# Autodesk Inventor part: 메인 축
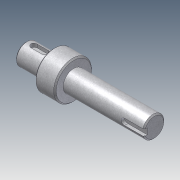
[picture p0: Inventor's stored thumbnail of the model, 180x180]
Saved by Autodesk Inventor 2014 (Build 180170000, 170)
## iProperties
Company: 한국ATC센터
Created: 2014-10
Part Number: 메인 축
Document SubType Name: Modeling
Designer: KYOUNG IL JANG
Density: 1 g/cm^3
Mass: 29.2926 g
Surface Area: 74.3518 cm^2
Volume: 29.2926 cm^3
Material: 일반
Appearance: 금속-강(스테인리스, 브러시됨)
Author: KYOUNG IL JANG
Revision Number: 1
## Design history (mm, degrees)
sketch "스케치1"
  geometry: L1 (10.497, -57.5)-(112.497, -57.5); L2 (10.497, -66)-(32.497, -66); L3 (32.497, -72.5)-(46.5, -72.5); L4 (46.5, -66)-(112.497, -66); L5 (112.497, -66)-(112.497, -57.5); L6 (10.497, -66)-(10.497, -57.5); L7 (46.5, -69.749)-(46.5, -45.251) reference; L8 (46.5, -72.5)-(46.5, -66); L9 (32.497, -72.5)-(32.497, -66); L10 (32.497, -35)-(32.497, -80) reference; 3 further points
  constraints: 16 end point, 3 point on line, 2 parallel, 2 perpendicular, 1 collinear, 1 horizontal, 1 midpoint
  dimensions: "d0" = 17 diameter of L4 L1; "d1" = 30 diameter of L3 L1; "d2" = 22 distance of L2.start L2.end; "d3" = 65.99692 distance of L4.start L4.end (derived); "d5" = 17 diameter of L2 L1; "d19" = 80 distance between parallel lines of L5 L9
revolve "회전1" sketch "스케치1" stored, may be unused: angle "d4" = 90 deg
chamfer "모따기1" distance "d6" = 1; stored, may be unused: second distance "d7" = 2, angle "d8" = 45 deg
node "작업 평면1"
sketch "스케치2"
  geometry: L1 (-11, -7.5)-(-11, 7.5) reference; L2 (-4.5, 2.5)-(4.5, 2.5); L3 (4.5, -2.5)-(-4.5, -2.5); A1 r 2.5 centre (4.5, 0) between (4.5, -2.5) and (4.5, 2.5); A2 r 2.5 centre (-4.5, 0) between (-4.5, 2.5) and (-4.5, -2.5); 2 further points
  constraints: 4 end point, 4 point on circle, 4 tangent, 2 centre point, 1 horizontal alignment, 1 midpoint, 1 parallel, 1 perpendicular
  dimensions: "d9" = 5 distance between parallel lines of L3 L2; "d10" = 14 dimension on A1 A2; "d11" = 4 distance edge to line of A2 L1
extrude "돌출1" cut sketch "스케치2" distance "d12" = 3; taper "d13" = 0 deg
node "작업 평면2"
sketch "스케치3"
  geometry: L1 (32.998, 7.5)-(32.998, -7.5) reference; L2 (32.998, 2.5)-(17.498, 2.5); L3 (17.498, -2.5)-(32.998, -2.5); A1 r 2.5 centre (17.498, 0) between (17.498, 2.5) and (17.498, -2.5); 2 further points
  constraints: 4 end point, 2 perpendicular, 2 point on circle, 2 point on line, 2 tangent, 1 centre point, 1 horizontal alignment, 1 midpoint
  dimensions: "d14" = 5 distance between parallel lines of L3 L2; "d15" = 18 dimension on A1 L1
extrude "돌출2" cut sketch "스케치3" distance "d16" = 3; taper "d17" = 0 deg
node "솔리드1"
node "참조4"
node "참조5"
